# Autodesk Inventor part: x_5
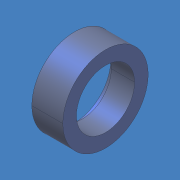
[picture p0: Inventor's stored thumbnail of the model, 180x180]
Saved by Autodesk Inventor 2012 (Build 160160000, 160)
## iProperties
Company: CAD-Verlag
Part Number: x_5
Document SubType Name: Modeling
Created: 2004-09
Material: Standard
Designer: Greiling
Manufacturer: Standard
Standards Organization: Custom
Density: 1 g/cm^3
Control State: 0
Master: False
Checked Out: False
Shininess: 64.0
Length Units: 11269
Angle Units: 11279
Time Units: 11290
Mass Units: 11283
Length Display Precision: 3
Angle Display Precision: 2
Compacted: True
Übersetzungsnorm: STEP AP214CD
Dateiname: w2c22665.stp
Vorprozessor: ACIS
Postprozessor: Build: 081d, Release: 8 SP1 - Date: Tue 01/26/2004
Gesendete Einheiten: MILLIMETERS
Unbestimmtheit: 1e-06
Density: 0.0
Volumn: 0.0
Area: 0.0
PropertySet Name: Model Information
Author: Jürgen Kronas
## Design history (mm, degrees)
feature "Basis1"
node "Volumenkörper1"
node "Volumenkörpern"
node "Oberflächenkörpern"
